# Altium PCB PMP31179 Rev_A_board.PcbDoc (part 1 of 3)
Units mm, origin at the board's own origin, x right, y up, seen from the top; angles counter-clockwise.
Board outline 218.44 x 102.26 mm, 4 copper layers (Top Layer, Mid-Layer 1, Mid-Layer 2, Bottom Layer), stack 1.473 mm thick; 246 components, 120 nets, 592 pads, 115 vias.
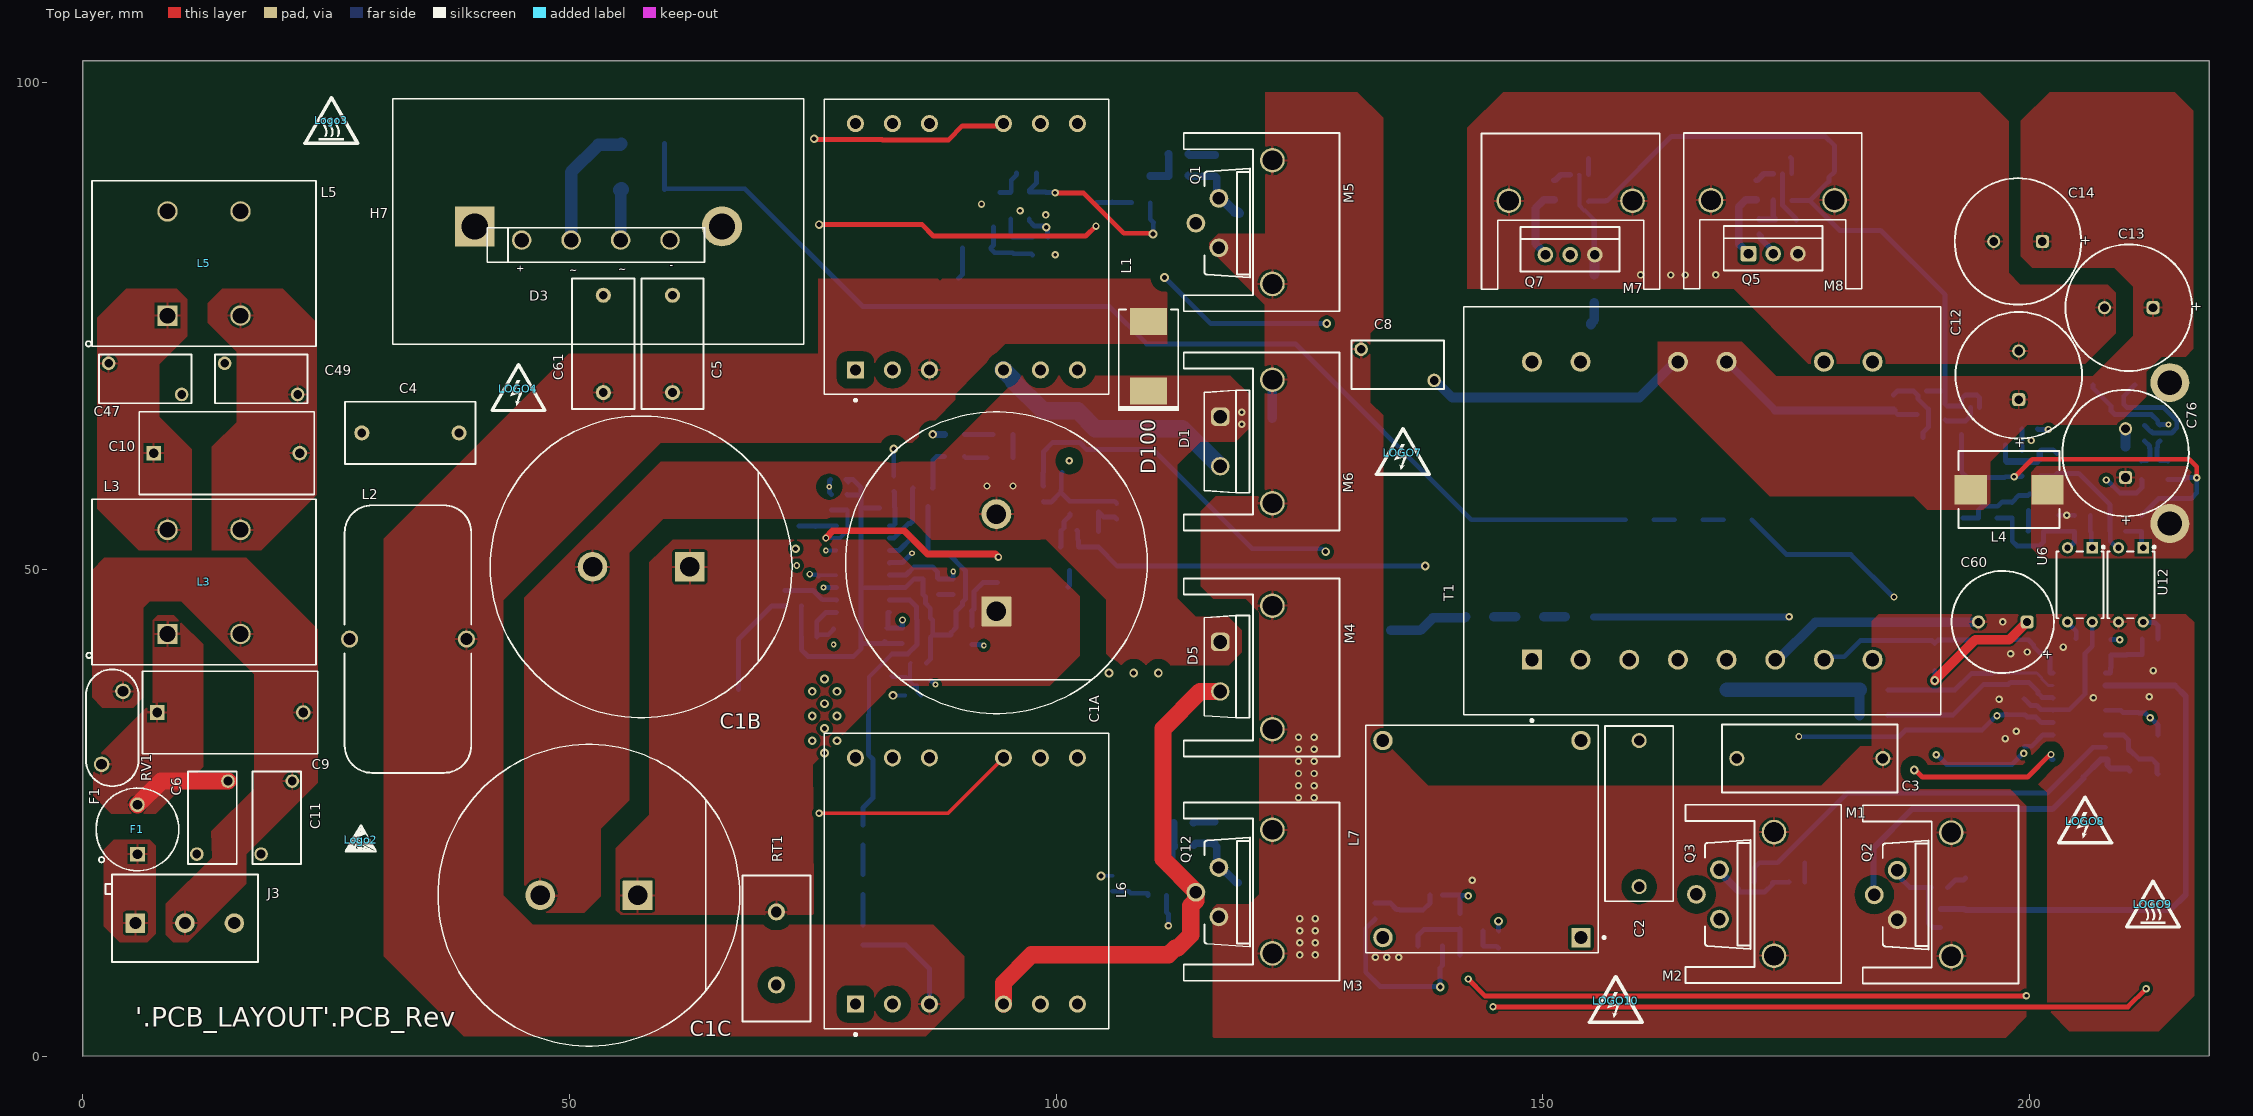
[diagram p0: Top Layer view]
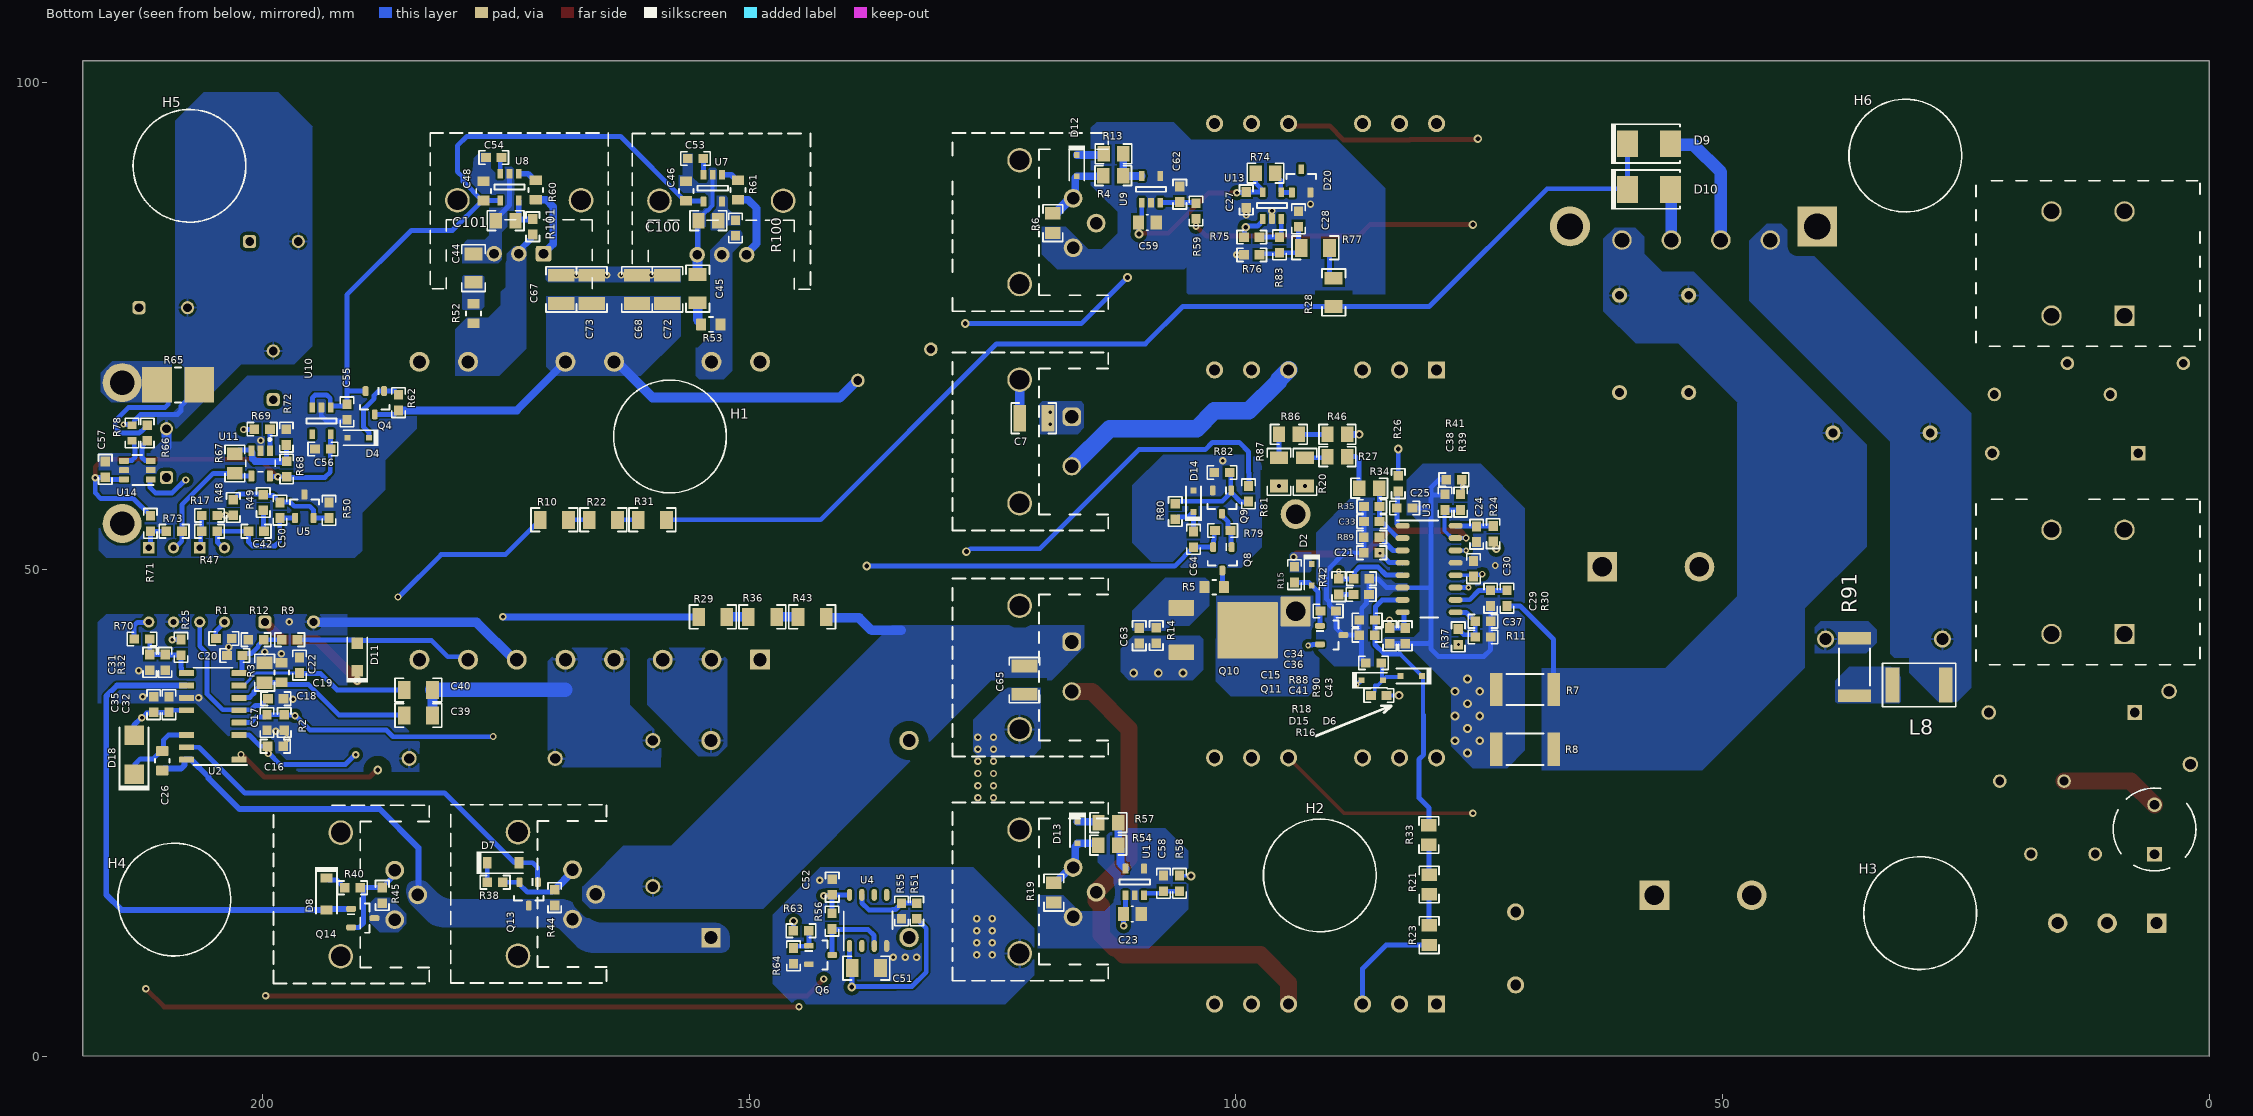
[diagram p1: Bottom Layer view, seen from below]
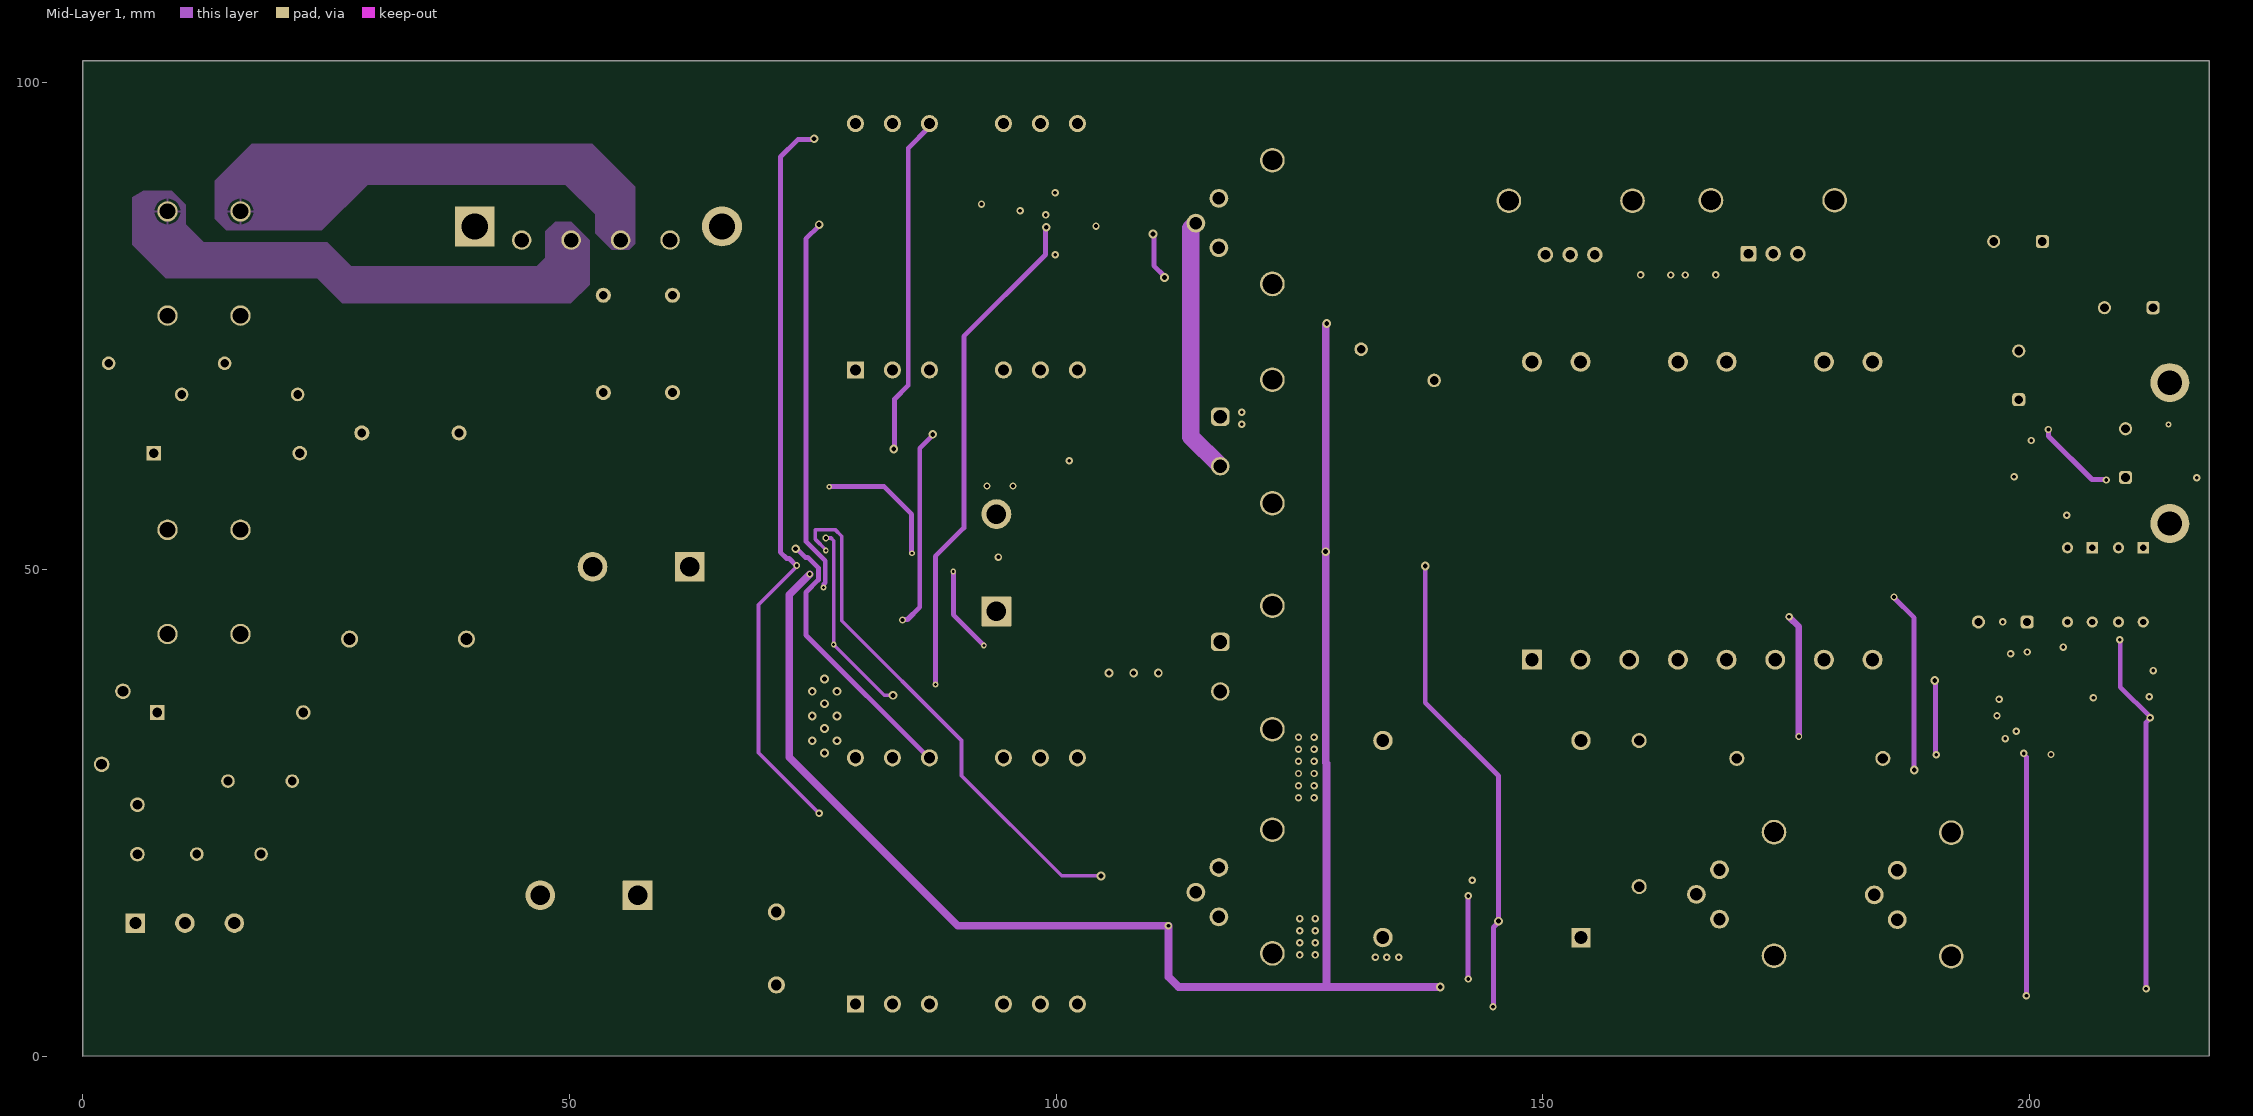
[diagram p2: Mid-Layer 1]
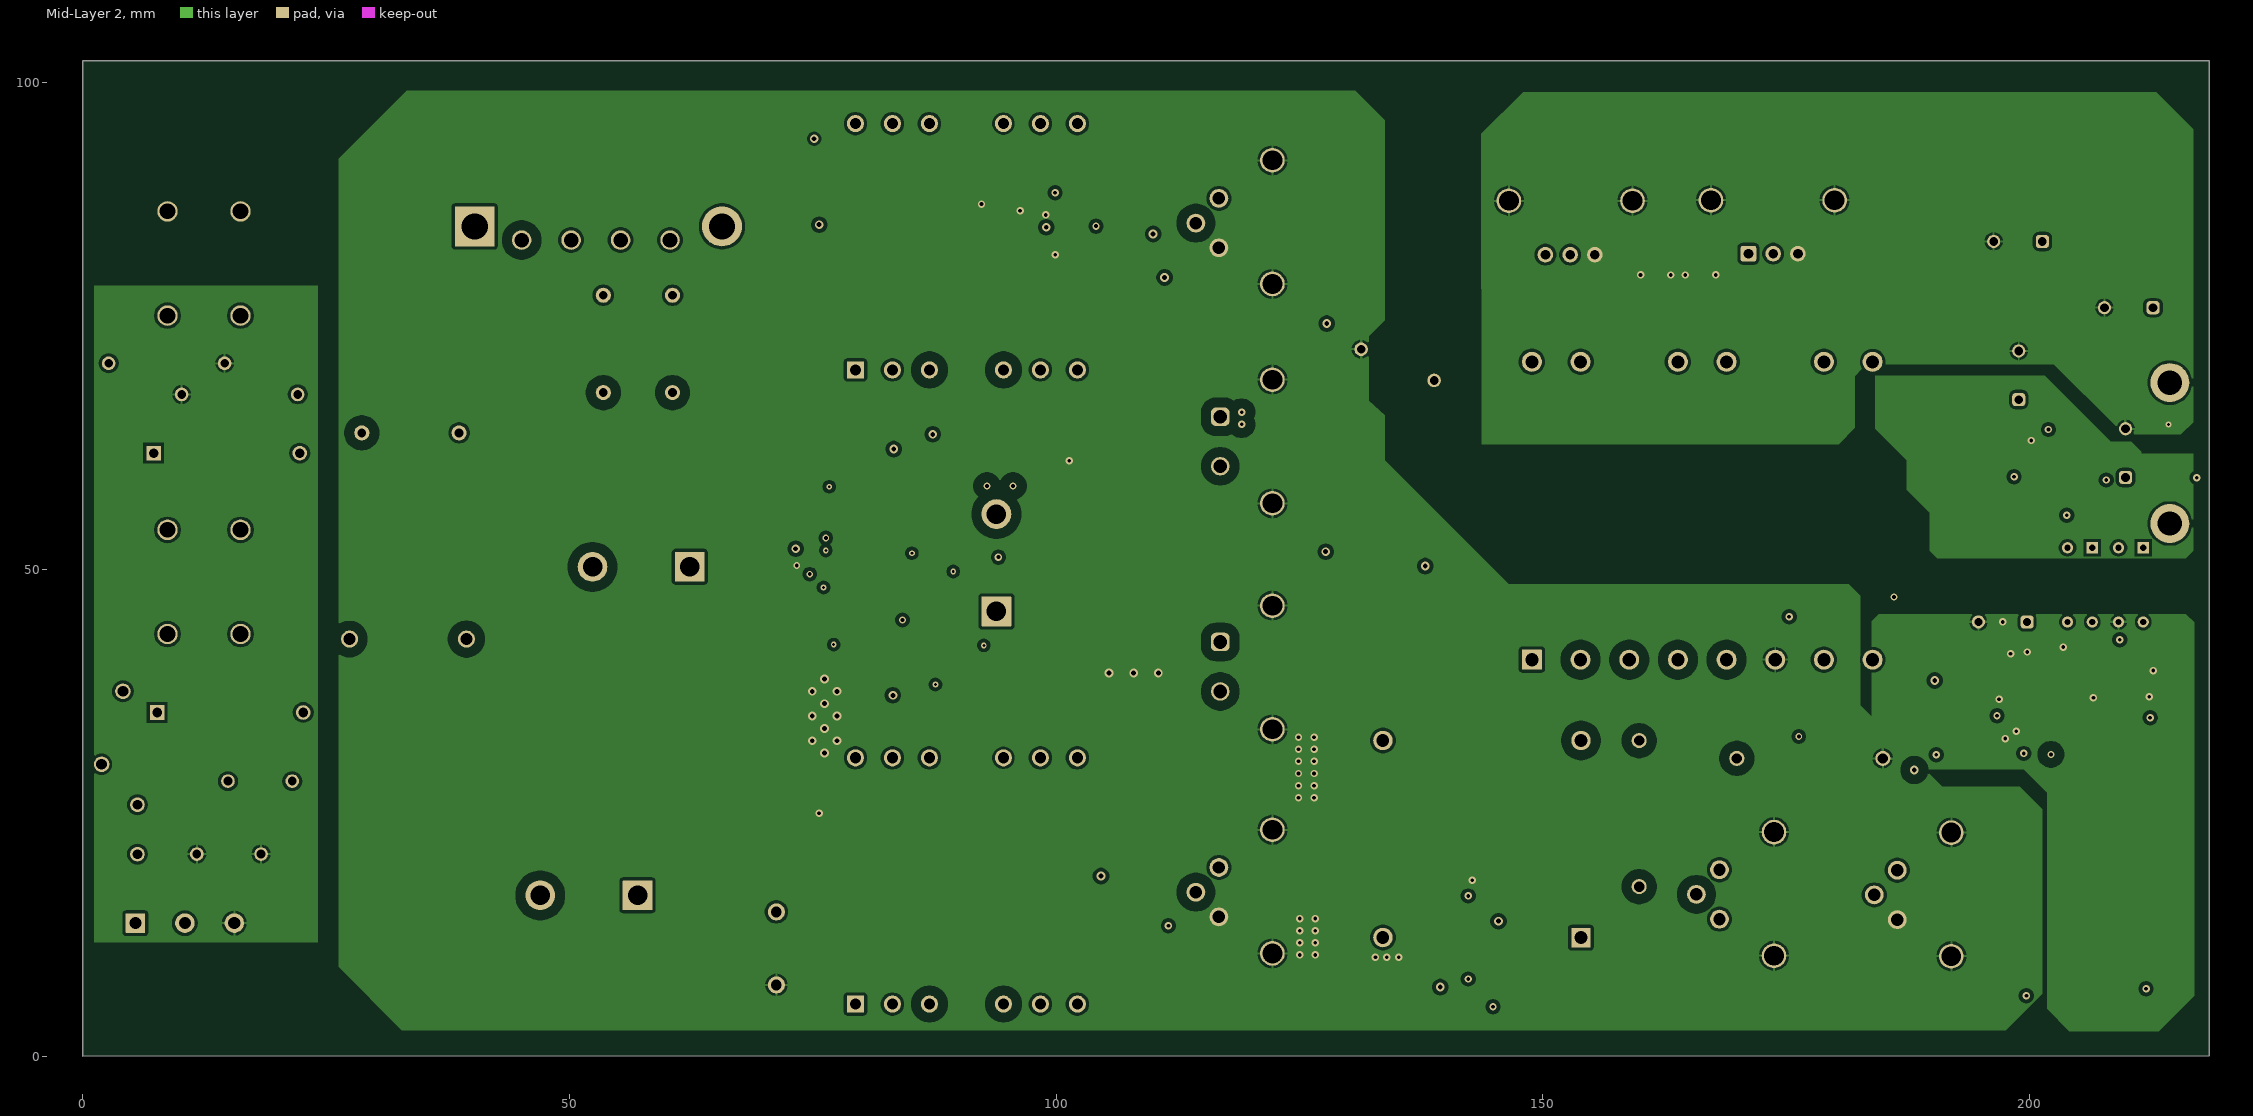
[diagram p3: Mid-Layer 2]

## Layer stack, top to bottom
Top Solder: solder mask 0.18, Solder Resist, Dk 3.5
Top Layer: signal copper 0.07
Dielectric1: prepreg 0.232, FR-4, Dk 4.8
Mid-Layer 1: signal copper 0.0356
Dielectric2: dielectric 0.71, FR-4, Dk 4.8
Mid-Layer 2: signal copper 0.0356
Dielectric3: dielectric 0.32, FR-4, Dk 4.8
Bottom Layer: signal copper 0.07
Bottom Solder: solder mask 0.018, Solder Resist, Dk 3.5

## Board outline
0,0 218.44,0.069 218.44,102.265 0,102.265

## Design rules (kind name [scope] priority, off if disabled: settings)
AcuteAngle [All] p1: minimum=4.50000000000000E+0001 checktracksonly=FALSE
AssemblyTestPointUsage [All] p1: valid=2
BoardOutlineClearance [All] p1: gap=0.381 ignorepadtopadclearanceinfootprint=FALSE
Clearance HV_ALL [InNetClass('HV')] p1: gap=1.016 ignorepadtopadclearanceinfootprint=FALSE
Clearance Clearance_1 [InNet('NetR10_2') vs InNet('PGND')] p2: gap=1.524 ignorepadtopadclearanceinfootprint=FALSE except(0: Arc-Hole Track-Hole SMDPad-Hole THPad-Hole Via-Hole Fill-Hole Poly-Hole Region-Hole Text-Hole)
Clearance Clearance_390V_Discrete [InNet('390V') vs InNet('NetR20_1') Or InNet('NetR86_2') Or InNet('NetQ3_1') Or InNet('SW') Or IsKeepOut] p3: gap=0.61 ignorepadtopadclearanceinfootprint=FALSE except(0: Arc-Hole Track-Hole SMDPad-Hole THPad-Hole Via-Hole Fill-Hole Poly-Hole Region-Hole Text-Hole)
Clearance Clearance_390V [InNet('390V')] p4: gap=1.5 ignorepadtopadclearanceinfootprint=FALSE except(0: Arc-Hole Track-Hole SMDPad-Hole THPad-Hole Via-Hole Fill-Hole Poly-Hole Region-Hole Text-Hole)
Clearance Clearance_MTG [InPadClass('MTG')] p5: gap=0.762 ignorepadtopadclearanceinfootprint=FALSE except(0: Arc-Hole Track-Hole SMDPad-Hole THPad-Hole Via-Hole Fill-Hole Poly-Hole Region-Hole Text-Hole)
Clearance Clearance_Keepouts [IsKeepOut] p6: gap=0.381 ignorepadtopadclearanceinfootprint=FALSE
Clearance Clearance_Poly [InPolygon] p7: gap=0.381 ignorepadtopadclearanceinfootprint=FALSE except(0: Arc-Hole Track-Hole SMDPad-Hole THPad-Hole Via-Hole Fill-Hole Poly-Hole Region-Hole Text-Hole; 0.203: Track-Poly SMDPad-Poly; 0.305: THPad-Poly; 0.508: Poly-Poly)
Clearance [All] p8: gap=0.203 ignorepadtopadclearanceinfootprint=FALSE
ComponentClearance ComponentClearance_MountingHoles_FiducialMarks [InComponentClass('Mounting Holes') vs InComponentClass('FiducialMark')] p1: gap=0.254 collisioncheckmode=3 verticalgap=0.254 showdistances=FALSE
ComponentClearance ComponentClearance_Shunt [InComponentClass('Header') vs InComponentClass('Shunt')] p2: gap=0 collisioncheckmode=3 verticalgap=0 showdistances=FALSE
ComponentClearance ComponentClearance_Logo [InComponentClass('Logo')] p3: gap=0.127 collisioncheckmode=3 verticalgap=0.127 showdistances=FALSE
ComponentClearance ComponentClearance_ScrewToNut [(HasFootprint('NY PMS 440 0025 PH')) vs (HasFootprint('Keystone_1902C'))] p4: gap=0.127 collisioncheckmode=3 verticalgap=0.127 showdistances=FALSE
ComponentClearance ComponentClearance_MountingHoles [InComponentClass('Mounting Holes')] p5: gap=1.27 collisioncheckmode=3 verticalgap=2540 showdistances=FALSE
ComponentClearance ComponentClearance_SmallPassives [HasFootprint('0201*') or HasFootprint('0402*') or HasFootprint('0508') or HasFootprint('0603*') or HasFootprint('0612') or HasFootprint('0805*') or HasFootprint('0815*') or HasFootprint('0830*') or HasFootprint('1206*') or HasFootprint('1210*') or HasFootprint('1808*') or HasFootprint('1812*') or HasFootprint('1825*') or HasFootprint('2010*') or HasFootprint('2220*') or HasFootprint('2225*') or HasFootprint('2512*') or HasFootprint('2728*') or HasFootprint('3518*') vs HasFootprint('0201*') or HasFootprint('0402*') or HasFootprint('0508') or HasFootprint('0603*') or HasFootprint('0612') or HasFootprint('0805*') or HasFootprint('0815*') or HasFootprint('0830*') or HasFootprint('1206*') or HasFootprint('1210*') or HasFootprint('1808*') or HasFootprint('1812*') or HasFootprint('1825*') or HasFootprint('2010*') or HasFootprint('2220*') or HasFootprint('2225*') or HasFootprint('2512*') or HasFootprint('2728*') or HasFootprint('3518*')] p6: gap=0.254 collisioncheckmode=3 verticalgap=0.254 showdistances=FALSE
ComponentClearance ComponentClearance_THtoSMT [IsThruComponent vs IsSMTComponent] p7: gap=0.127 collisioncheckmode=3 verticalgap=0.127 showdistances=FALSE
ComponentClearance ComponentClearance_THtoTH [IsThruComponent vs IsThruComponent] p8: gap=0.254 collisioncheckmode=3 verticalgap=0.254 showdistances=FALSE
ComponentClearance [All] p9: gap=0.254 collisioncheckmode=3 verticalgap=0.254 showdistances=FALSE
DiffPairsRouting [All] p1: maxlimit=2.54 minlimit=0.254 mostfreqgap=0.254 toplayer_minwidth=0.381 toplayer_maxwidth=0.381 toplayer_prefwidth=0.381 midlayer1_minwidth=0.381 midlayer1_maxwidth=0.381 midlayer1_prefwidth=0.381 midlayer2_minwidth=0.381 midlayer2_maxwidth=0.381 midlayer2_prefwidth=0.381 bottomlayer_minwidth=0.381 bottomlayer_maxwidth=0.381 bottomlayer_prefwidth=0.381 maxuncoupledlength=25.4
FabricationTestPointUsage TestPointUsage [All] p1: valid=2 allowmultiple=FALSE
FabricationTestpoint Testpoint [All] p1: side=3 testpointundercomponent=TRUE minsize=1.016 maxsize=2.54 preferedsize=1.524 minholesize=0 maxholesize=1.016 preferedholesize=0.813 testpointgrid=0.025 allowsidetop=TRUE allowsidebottom=TRUE usegrid=TRUE gridtolerance=0
FanoutControl Fanout_LCC [IsLCC] p1: bgadir=Out bgaviamode=Centered fanoutstyle=Auto fanoutdirection=Alternating viagrid=0.025 // Fanout_LCC (Default Rule)
FanoutControl Fanout_BGA [IsBGA] p2: bgadir=Out bgaviamode=Centered fanoutstyle=Auto fanoutdirection=Alternating viagrid=0.025 // Fanout_BGA (Default Rule)
FanoutControl Fanout_Default [All] p4: bgadir=Out bgaviamode=Centered fanoutstyle=Auto fanoutdirection=Alternating viagrid=0.025 // Fanout_Default (Default Rule)
FanoutControl Fanout_Small [(CompPinCount < 5)] p5: bgadir=Out bgaviamode=Centered fanoutstyle=Auto fanoutdirection=OutThenIn viagrid=0.025 // Fanout_Small (Default Rule)
Height [All] p1: minheight=0 maxheight=38 prefheight=12.7
HoleSize [All] p1: absolutevalues=TRUE maxlimit=6.375 minlimit=0.2 maxpercent=80.000 minpercent=20.000
MinimumAnnularRing MinimumAnnularRing_ThermalPadVias [IsVia and InAnyComponent] p1: minimumring=0.15
MinimumAnnularRing [All] p2: minimumring=0.127
MinimumSolderMaskSliver MinimumSolderMaskSliver_Logo [InComponentClass('Logo') vs InComponentClass('Logo')] p1: minsoldermaskwidth=0.018
MinimumSolderMaskSliver [All] p2: minsoldermaskwidth=0.1
PlaneConnect [All] p1: planeconnectstyle=Relief reliefexpansion=0.254 reliefentries=4 reliefconductorwidth=0.254 reliefairgap=0.254
PolygonConnect [All] p1: thpad.connectstyle=Relief thpad.reliefconductorwidth=0.254 thpad.reliefentries=4 thpad.polygonreliefangle="90 Angle" thpad.airgapwidth=0.254 smdpad.connectstyle=Direct smdpad.reliefconductorwidth=0.254 smdpad.reliefentries=4 smdpad.polygonreliefangle="90 Angle" smdpad.airgapwidth=0.254 via.connectstyle=Direct via.reliefconductorwidth=0.254 via.reliefentries=4 via.polygonreliefangle="90 Angle" via.airgapwidth=0.254
RoutingVias [All] p1: holewidth=0.381 width=0.762 viastyle="Through Hole" minholewidth=0.2 minwidth=0.5 maxholewidth=1.016 maxwidth=1.651
RoutingVias ThermalPadVias [IsVia and InAnyComponent] p2: holewidth=0.2 width=0.5 viastyle="Through Hole" minholewidth=0.2 minwidth=0.5 maxholewidth=0.33 maxwidth=0.6
SilkToBoardRegionClearance [Not ((IsComment or IsDesignator) And (Hide <> 'False')) and not InRegion(1000,500,4000,800)] p1:
SilkToSilkClearance SilkToSilkClearance_Pb-FreeLogo [(HasFootprint('Pb-Free_Overlay_Medium') OR HasFootprint('Pb-Free_Overlay_Small')) vs (HasFootprint('Pb-Free_Overlay_Medium') OR HasFootprint('Pb-Free_Overlay_Small'))] p1: silktosilkclearance=0
SilkToSilkClearance [All] p2: silktosilkclearance=0.102
SilkToSolderMaskClearance SilkToComponentPadClearance [IsPad and InAnycomponent] p1: minsilkscreentomaskgap=0.127 clearancetoexposedcopper=TRUE
SilkToSolderMaskClearance "Silk to Solder Mask Opening" [All] p2: minsilkscreentomaskgap=0.102 clearancetoexposedcopper=FALSE
SolderMaskExpansion [All] p1: expansion=0.064 istentingtop=FALSE
Width [All] p1: maxlimit=2.54 minlimit=0.152 preferedwidth=0.254 checkconnectedcopper=TRUE
14 further rules are at their usual default settings.

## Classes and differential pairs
net class HV: NetA NetC2_2 NetC4_1 NetD1_3 NetD5_3 NetL7_6 NetR10_2 VAC Vpfc
component class "PMP30763 Rev_D PFC Schematic": C1A C1B C1C C4 C5 C6 C7 C9 C10 C11 C15 C21 C23 C24 C25 C27 C28 C29 C30 C33 C34 C36 C37 C38 C41 C43 C47 C49 C58 C59 C61 C62 C63 C64 C65 D1 D2 D3 D5 D6 D9 D10 D12 D13 D14 D15 D20 D100 F1 H7 J3 L1 L2 L3 L5 L6 L8 M1 M2 M3 M4 M5 M6 Q1 Q8 Q9 Q10 Q11 Q12 R4 R5 R6 R7 R8 R11 R13 R14 R15 R16 R18 R19 R20 R21 R23 R24 R26 R27 R28 R30 R33 R34 R35 R37 R39 R41 R42 R46 R54 R57 R58 R59 R74 R75 R76 R77 R79 R80 R81 R82 R83 R86 R87 R88 R89 R90 R91 RT1 RV1 U1 U3 U9 U13
component class "PMP30763 Rev_D LLC Schematic": C2 C3 C8 C12 C13 C14 C16 C17 C18 C19 C20 C22 C26 C31 C32 C35 C39 C40 C42 C44 C45 C46 C48 C50 C51 C52 C53 C54 C55 C56 C57 C60 C67 C68 C72 C73 C76 C100 C101 D4 D7 D8 D11 D18 L4 L7 M7 M8 Q2 Q3 Q4 Q5 Q6 Q7 Q13 Q14 R1 R2 R3 R9 R10 R12 R17 R22 R25 R29 R31 R32 R36 R38 R40 R43 R44 R45 R47 R48 R49 R50 R51 R52 R53 R55 R56 R60 R61 R62 R63 R64 R65 R66 R67 R68 R69 R70 R71 R72 R73 R78 R100 R101 T1 U2 U4 U5 U6 U7 U8 U10 U11 U12 U14
component class "PMP30763 Rev_C Hardware": !PCB1 H1 H2 H3 H4 H5 H6 H8 H9 H10 H11 Logo2 LOGO3 LOGO4 LOGO7 LOGO8 LOGO9 LOGO10

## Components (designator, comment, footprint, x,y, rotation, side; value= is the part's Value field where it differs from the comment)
C1A "LGN2V271MELB25" FP-ESMR451VSN221MR25S_RADIAL-MFG 93.853,50.703 r90 top value=270µF
C1B "LGN2V271MELB25" FP-ESMR451VSN221MR25S_RADIAL-MFG 57.361,50.28 r180 top value=270µF
C1C "LGN2V271MELB25" FP-ESMR451VSN221MR25S_RADIAL-MFG 51.99,16.54 r180 top value=270µF
C2 "B32642B6683J" B32652_1800x700x1250 159.887,24.929 r90 top value=0.068uF
C3 "B32642B6683J" B32652_1800x700x1250 177.412,30.607 r0 top value=0.068uF
C4 "ECW-FE2W334K" R46_1300x1200x600 33.655,64.042 r0 top value=0.33µF
C5 "ECW-FE2W334K" R46_1300x1200x600 60.579,73.182 r90 top value=0.33µF
C6 "Capacitor" AY2_950x500_Straight 13.31,24.524 r270 top value=2200pF
C7 "VJ1210Y103KXEAT5Z" 1210 120.746,65.553 r0 bottom value=0.01uF
C8 "Capacitor" AY2_950x500_Straight 135.071,71.039 r180 top value=2200pF
C9 "Capacitor" B32922_14.5mm 15.138,35.319 r0 top value=0.33uF
C10 "Capacitor" B32922_14.5mm 14.783,61.964 r0 top value=0.33uF
C11 "Capacitor" AY2_950x500_Straight 19.914,24.524 r90 top value=2200pF
C12 "EEU-FS1H681B" Panasonic_1250x2500 198.878,69.959 r90 top value=680uF
C13 "EEU-FS1H681B" Panasonic_1250x2500 210.181,76.905 r180 top value=680uF
C14 "EEU-FS1H681B" Panasonic_1250x2500 198.802,83.712 r180 top value=680uF
C15 "Capacitor" 0603#1 90.505,45.733 r180 bottom value=1uF
C16 "C1608X7R1H104K080AA" 0603#1 198.659,31.854 r180 bottom value=0.1uF
C17 "GRM188R71C103KA01D" 0603#1 199.517,34.29 r270 bottom value=0.01uF
C18 "885012006023" 0603#1 198.616,36.733 r180 bottom value=100pF
C19 "Capacitor" 0805_HV1 198.021,39.428 r90 bottom value=3.3pF
C20 "Capacitor" 0603#1 202.837,41.169 r0 bottom value=10pF
C21 "GRM1885C1H122JA01D" 0603#1 86.042,51.731 r0 bottom value=1200pF
C22 "GRM188R71H822KA01D" 0603#1 196.182,40.178 r90 bottom value=8200pF
C23 "08053C225KAT2A" 0805_150 110.617,14.605 r180 bottom value=2.2uF
C24 "C0603C330J5GACTU" 0603#1 75.255,53.631 r270 bottom value=33pF
C25 "C0603C330J5GACTU" 0603#1 82.651,56.316 r180 bottom value=33pF
C26 "Capacitor" 0805_HV1 210.287,30.356 r270 bottom value=0.1uF
C27 "C1608X7R1H104K080AA" 0603#1 98.922,87.984 r270 bottom value=0.1uF
C28 "C1608X7R1H104K080AA" 0603#1 93.563,86.025 r90 bottom value=0.1uF
C29 "C1608X7R1H102K" 0603#1 73.818,47.071 r270 bottom value=1000pF
C30 "Capacitor" 0603#1 75.565,50.093 r270 bottom value=1uF
C31 "C1608X7R1H474K080AC" 0603#1 211.561,40.466 r270 bottom value=0.47uF
C32 "C1608X7R1H104K080AA" 0603#1 209.594,36.134 r90 bottom value=0.1uF
C33 "GRM1885C1H471JA01D" 0603#1 86.028,54.945 r0 bottom value=470pF
C34 "GRM188R71C103KA01D" 0603#1 87.084,49.052 r180 bottom value=0.01uF
C35 "GRM188R61E475KE11D" 0603#1 211.167,36.134 r270 bottom value=4.7uF
C36 "CL10B684KO8NFNC" 0603#1 87.114,47.452 r180 bottom value=0.68uF
C37 "DNP" 0603#1 74.597,44.684 r180 bottom
C38 "GRM188R71H224KAC4D" 0603#1 78.499,56.934 r90 bottom value=0.22uF
C39 "Capacitor" 1206 183.973,35.022 r0 bottom value=150pF
C40 "GRM31A7U3A820JW31D" 1206 183.973,37.638 r0 bottom value=82pF
C41 "C1608X7R2A102K080AA" 0603#1 86.517,43.265 r0 bottom value=1000pF
C42 "06033C473JAT2A" 0603#1 200.629,53.943 r0 bottom value=0.047uF
C43 "Capacitor" 0603#1 82.585,43.19 r270 bottom value=680pF
C44 "12061A331JAT2A" 1206 178.308,80.977 r270 bottom value=330pF
C45 "12061A331JAT2A" 1206 155.276,78.859 r270 bottom value=330pF
C46 "Capacitor" 0805_HV1 156.464,88.9 r90 bottom value=1uF
C47 "Capacitor" AY2_950x500_Straight 6.401,69.591 r0 top value=2200pF
C48 "Capacitor" 0805_HV1 177.276,88.907 r90 bottom value=1uF
C49 "Capacitor" AY2_950x500_Straight 18.317,69.591 r0 top value=2200pF
C50 "Capacitor" 0603#1 198.192,56.102 r270 bottom value=10pF
C51 "Capacitor" 1206 137.951,9.059 r180 bottom value=1uF
C52 "C1608X7R1H104K080AA" 0603#1 141.459,17.386 r90 bottom value=0.1uF
C53 "GRM188R6YA225KA12D" 0603#1 155.501,92.23 r0 bottom value=2.2uF
C54 "GRM188R6YA225KA12D" 0603#1 176.225,92.331 r0 bottom value=2.2uF
C55 "Capacitor" 0603#1 191.309,66.196 r270 bottom value=1uF
C56 "GRM188R61E475KE11D" 0603#1 193.778,62.378 r0 bottom value=4.7uF
C57 "Capacitor" 0603#1 216.132,60.298 r90 bottom value=1uF
C58 "06035A101JAT2A" 0603#1 107.428,17.761 r90 bottom value=100pF
C59 "08053C225KAT2A" 0805_150 109.076,85.67 r180 bottom value=2.2uF
C60 "EEU-FS1V102LB" Panasonic_1000x1250 197.238,44.621 r180 top value=1000µF
C61 "ECW-FE2W334K" R46_1300x1200x600 53.467,73.182 r90 top value=0.33µF
C62 "06035A101JAT2A" 0603#1 105.758,88.559 r90 bottom value=100pF
C63 "C1608X7R1H104K080AA" 0603#1 109.923,43.211 r270 bottom value=0.1uF
C64 "C1608X7R1H474K080AC" 0603#1 104.346,53.104 r90 bottom value=0.47uF
C65 "VJ1210Y103KXEAT5Z" 1210 121.711,38.65 r270 bottom value=0.01uF
C67 "Capacitor" 1210 169.285,78.785 r90 bottom value=4.7uF
C68 "Capacitor" 1210 161.513,78.785 r90 bottom value=4.7uF
C72 "Capacitor" 1210 158.388,78.785 r90 bottom value=4.7uF
C73 "Capacitor" 1210 166.161,78.785 r90 bottom value=4.7uF
C76 "EEU-FS1H681B" Panasonic_1250x2500 209.851,61.969 r90 top value=680uF
C100 "GRM21A5C2E101JW01D" 0805_HV 154.178,85.852 r0 bottom value=100pF
C101 "GRM21A5C2E101JW01D" 0805_HV 175.006,85.852 r0 bottom value=100pF
D1 "MUR860G" TO-220AC 116.848,63.158 r270 top
D2 "BAT54HT1G" SOD-323 92.197,49.479 r270 bottom
D3 "GBU2510-G" GBU 52.705,83.85 r0 top
D4 "BZX384-C15,115" SOD-323 190.137,63.542 r0 bottom value=15V
D5 "MUR860G" TO-220AC 116.848,40.022 r270 top
D6 "BAT54HT1G" SOD-323 81.961,39.07 r0 bottom
D7 "DIODE_SCHOTTKY" SOD-123 175.254,19.883 r180 bottom value=SD103BW-7-F
D8 "DIODE_SCHOTTKY" SOD-123 193.411,16.683 r270 bottom value=SD103BW-7-F
D9 "DIODE" SMB 57.531,93.756 r180 bottom value=RS1MB-13-F
D10 "DIODE" SMB 57.531,89.057 r180 bottom value=RS1MB-13-F
D11 "PMEG6010CEH,115" SOD-123F 190.246,41.021 r90 bottom
D12 "BAT54HT1G" SOD-323 116.326,91.501 r270 bottom
D13 "BAT54HT1G" SOD-323 116.245,22.994 r270 bottom
D14 "BAS20HT1G" SOD-323 104.346,57.029 r90 bottom
D15 "BAT54HT1G" SOD-323 85.979,38.638 r180 bottom
D18 "DIODE" SMA 213.181,30.988 r90 bottom value=US1J-13-F
D20 "LM4040D50QDBZRG4" DBZ0003A_N 93.275,89.94 r90 bottom value=LM4040D50
D100 "S3J-E3/57T" SMC 109.474,71.912 r90 top
F1 "38321000000" FUSE_38321000000 5.613,23.305 r90 top value=10A
H1 "Bumpon" Bumpon_SJ5003Transparent 158.118,63.673 r180 bottom
H2 "Bumpon" Bumpon_SJ5003Transparent 91.364,18.581 r180 bottom
H3 "Bumpon" Bumpon_SJ5003Transparent 29.688,14.709 r180 bottom
H4 "Bumpon" Bumpon_SJ5003Transparent 209.041,16.093 r180 bottom
H5 "Bumpon" Bumpon_SJ5003Transparent 207.484,91.482 r180 bottom
H6 "Bumpon" Bumpon_SJ5003Transparent 31.217,92.532 r180 bottom
H7 "V9733E1-LP" FP-V9733E1-LP_THERMAL_HEATSINK_25MM0_42MM0-MFG 52.959,85.755 r0 top
J3 "ED120/3DS" On-Shore_ED120_3DS 10.482,13.68 r0 top
L1 "750318973r00" FP-750318973r00_PTH_30MM35_29MM2-MFG 90.775,83.165 r90 top value=150µH
L2 "7447076" WE-FI_2750x1300 33.401,42.858 r0 top value=150uH
L3 "7448031501" WURTH_7448031501 12.446,48.73 r0 top value=1mH
L4 "PA2607.301NLT" PA2607NL_7R5mm 197.887,58.21 r0 top value=300nH
L5 "7448031501" WURTH_7448031501 12.446,81.446 r0 top value=1mH
L6 "750318973r00" FP-750318973r00_PTH_30MM35_29MM2-MFG 90.775,18.014 r90 top value=150µH
L7 "750318974r00" FP-750318974r00_PTH_23MM88_23MM36-MFG 143.733,22.322 r180 top value=17uH
L8 "74455122" WE-PD4-S 29.797,38.142 r0 bottom value=22uH
Logo2 "ESD Susceptible" ESD_Overlay_Small 28.53,22.255 r0 top
Logo3 "CAUTION HOT SURFACE" IEC_HotSurface_Small 25.527,96.139 r0 top (schematic designator LOGO3)
LOGO4 "DANGER HIGH VOLTAGE" IEC_HighVoltage_Small 44.755,68.579 r0 top
LOGO7 "DANGER HIGH VOLTAGE" IEC_HighVoltage_Small 135.605,62.008 r0 top
LOGO8 "DANGER HIGH VOLTAGE" IEC_HighVoltage_Small 205.696,24.163 r0 top
LOGO9 "CAUTION HOT SURFACE" IEC_HotSurface_Small 212.665,15.644 r0 top
LOGO10 "DANGER HIGH VOLTAGE" IEC_HighVoltage_Small 157.48,5.715 r0 top
M1 "WA-T220-101E" HEATSINK_WA-T220-101E 190.85,16.632 r180 top
M2 "WA-T220-101E" HEATSINK_WA-T220-101E 172.638,16.683 r180 top
M3 "WA-T220-101E" HEATSINK_WA-T220-101E 121.105,16.919 r180 top
M4 "WA-T220-101E" HEATSINK_WA-T220-101E 121.105,39.942 r180 top
M5 "WA-T220-101E" HEATSINK_WA-T220-101E 121.105,85.695 r180 top
M6 "WA-T220-101E" HEATSINK_WA-T220-101E 121.105,63.158 r180 top
M7 "WA-T220-101E" HEATSINK_WA-T220-101E 152.847,86.79 r270 top
M8 "WA-T220-101E" HEATSINK_WA-T220-101E 173.609,86.844 r270 top
Q1 "IPA60R120P7XKSA1" TO-220AB 116.711,85.593 r270 top
Q2 "IPP60R190P6" TO-220AB 186.405,16.581 r270 top value=IPP60R070CFD7
Q3 "IPP60R190P6" TO-220AB 168.132,16.631 r270 top value=IPP60R070CFD7
Q4 "MMBTA05LT1G" SOT-23 188.451,67.136 r270 bottom
Q5 "CSD19531KCS" KCS0003B#1 173.652,82.452 r90 top
Q6 "MMBT2222LT1G" SOT-23 142.653,10.404 r180 bottom
Q7 "CSD19531KCS" KCS0003B#2 152.793,82.352 r90 top
Q8 "BSS84-7-F" SOT-23 101.375,51.11 r270 bottom
Q9 "MMBT3904LT1G" SOT-23 101.409,56.934 r270 bottom
Q10 "IPD60R360P7SAUMA1" DPAK 102.184,43.777 r180 bottom value=IPD60R360P7S
Q11 "MMBT3906-7-F" SOT-23 90.142,43.269 r180 bottom
Q12 "IPA60R120P7XKSA1" TO-220AB 116.711,16.859 r270 top
Q13 "BC858C-7-F" SOT-23 172.638,16.683 r270 bottom
Q14 "BC858C-7-F" SOT-23 189.681,14.194 r180 bottom
R1 "RMCF0603ZT0R00" 0603#1 203.955,42.921 r0 bottom value=0
R2 "ERJ-3EKF4531V" 0603#1 197.739,34.29 r90 bottom value=4.53k
R3 "CRCW0805150RFKEA" 0805_HV 199.774,39.409 r270 bottom value=150
R4 "ERJ-6GEYJ180V" 0805_HV 112.583,90.48 r0 bottom value=18
R5 "Resistor" 0805_HV1 102.216,48.197 r180 bottom value=18.2
R6 "Resistor" 0805_HV 118.79,85.595 r90 bottom value=10.0k
R7 "Resistor" 2512 70.29,37.69 r180 bottom value=0.03
R8 "Resistor" 2512 70.29,31.544 r180 bottom value=0.03
R9 "CRCW060344K2FKEA" 0603#1 197.198,42.794 r180 bottom value=44.2k
R10 "Resistor" 1206 169.996,55.118 r0 bottom value=1.00k
R11 "RMCF0603ZT0R00" 0603#1 74.597,43.087 r0 bottom value=0
R12 "RC0603FR-078K06L" 0603#1 200.653,42.794 r180 bottom value=8.06k
R13 "RC0805JR-072R2L" 0805_HV 112.558,92.702 r0 bottom value=2.2
R14 "ERJ-3EKF4992V" 0603#1 108.16,43.225 r270 bottom value=49.9k
R15 "CRCW0603100KFKEA" 0603#1 93.955,49.479 r270 bottom value=100k
R16 "RC0603FR-0744K2L" 0603#1 85.302,37.056 r180 bottom value=44.2k
R17 "RC0603FR-0712KL" 0603#1 205.425,55.569 r180 bottom value=12.0k
R18 "CRCW060351K1FKEA" 0603#1 85.852,40.416 r180 bottom value=51.1k
R19 "Resistor" 0805_HV 118.688,16.81 r90 bottom value=10.0k
R20 "CRCW12063M00JNEA" 1206 92.888,60.033 r270 bottom value=3.0Meg
R21 "RC0805FR-072M2L" 0805_HV 80.137,17.653 r270 bottom value=2.20Meg
R22 "Resistor" 1206 164.967,55.118 r0 bottom value=1.00k
R23 "RC0805FR-072M2L" 0805_HV 80.137,12.446 r270 bottom value=2.20Meg
R24 "CRCW06036K81FKEA" 0603#1 73.559,53.687 r270 bottom value=6.81k
R25 "RT0603DRE07213KL" 0603#1 208.349,42.007 r90 bottom value=213k
R26 "CRCW06036K81FKEA" 0603#1 83.31,58.833 r90 bottom value=6.81k
R27 "Resistor" 0805_HV 89.56,61.604 r0 bottom value=2.74Meg
R28 "Resistor" 1206 89.94,78.474 r90 bottom value=511k
R29 "Resistor" 1206 153.726,45.145 r180 bottom value=330k
R30 "Resistor" 0603#1 72.14,47.071 r90 bottom value=100
R31 "Resistor" 1206 159.938,55.118 r0 bottom value=1.00k
R32 "RC0603FR-07120KL" 0603#1 209.986,40.466 r90 bottom value=120k
R33 "RC0805FR-072M2L" 0805_HV 80.158,22.733 r90 bottom value=2.20Meg
R34 "Resistor" 0805_HV 86.282,58.374 r0 bottom value=2.74Meg
R35 "RT0603DRE07215KL" 0603#1 86.028,56.469 r180 bottom value=215k
R36 "Resistor" 1206 148.621,45.145 r180 bottom value=330k
R37 "DNP" 0603#1 77.135,43.087 r270 bottom
R38 "Resistor" 0603#1 176.092,17.877 r180 bottom value=22
R39 "RC0603FR-07200KL" 0603#1 76.899,56.934 r270 bottom value=200k
R40 "Resistor" 0603#1 190.735,17.322 r180 bottom value=22
R41 "CRCW060380K6FKEA" 0603#1 77.586,59.238 r0 bottom value=80.6k
R42 "RC0603FR-0727KL" 0603#1 89.416,48.252 r270 bottom value=27.0k
R43 "CRCW1206330KJNEA" 1206 143.516,45.145 r180 bottom value=330k
R44 "Resistor" 0603#1 169.971,16.302 r90 bottom value=4.7k
R45 "Resistor" 0603#1 187.675,16.531 r90 bottom value=4.7k
R46 "Resistor" 0805_HV 89.56,63.894 r0 bottom value=2.74Meg
R47 "Resistor" 0603#1 205.43,53.944 r0 bottom value=6.04k
R48 "Resistor" 0603#1 202.993,56.382 r270 bottom value=147k
R49 "Resistor" 0603#1 199.898,56.889 r90 bottom value=10.0k
R50 "RC0603FR-0713K3L" 0603#1 193.163,56.089 r270 bottom value=13.3k
R51 "CRCW0603113KFKEA" 0603#1 132.76,14.93 r270 bottom value=113k
R52 "Resistor" 0805_HV1 178.308,76.312 r90 bottom value=10
R53 "Resistor" 0805_HV1 153.924,75.184 r0 bottom value=10
R54 "ERJ-6GEYJ180V" 0805_HV 113.099,21.689 r0 bottom value=18
R55 "Resistor" 0603#1 134.335,14.93 r90 bottom value=10.0k
R56 "RT0603BRD07100KL" 0603#1 141.47,13.885 r90 bottom value=100k
R57 "RC0805JR-072R2L" 0805_HV 113.085,24.002 r0 bottom value=2.2
R58 "ERJ-3EKF1000V" 0603#1 105.777,17.761 r270 bottom value=100
R59 "ERJ-3EKF1000V" 0603#1 104.084,86.838 r270 bottom value=100
R60 "Resistor" 0805_HV1 171.907,89.003 r90 bottom value=4.7
R61 "Resistor" 0805_HV1 151.137,89.001 r270 bottom value=4.7
R62 "RC0603FR-076K81L" 0603#1 186.012,67.154 r270 bottom value=6.81k
R63 "CRCW0603113KFKEA" 0603#1 144.66,12.889 r180 bottom value=113k
R64 "Resistor" 0603#1 145.434,10.32 r90 bottom value=10.0k
R65 "WSL2512L5000FEA18" WSL2512_-0005 208.657,68.98 r0 bottom value=0.0005
R66 "CRCW060310R0FKEAHP" 0603#1 211.812,64.027 r270 bottom value=10.0
R67 "CRCW08051M00FKEA" 0805_HV 202.815,60.903 r270 bottom value=1.00Meg
R68 "MCT06030C1004FP500" 0603#1 197.503,60.333 r270 bottom value=1.00Meg
R69 "ERJ-3EKF3303V" 0603#1 200.021,64.43 r180 bottom value=330k
R70 "Resistor" 0603#1 212.362,42.871 r180 bottom value=487k
R71 "Resistor" 0603#1 211.502,54.743 r90 bottom value=6.04k
R72 "RT0603DRE07234KL" 0603#1 197.532,63.61 r270 bottom value=234k
R73 "Resistor" 0603#1 209.063,53.944 r0 bottom value=6.04k
R74 "Resistor" 0805_HV 96.941,90.728 r0 bottom value=10.0k
R75 "CRCW06031M10FKEA" 0603#1 98.354,84.154 r0 bottom value=1.10Meg
R76 "CRCW060390K9FKEA" 0603#1 98.354,82.331 r180 bottom value=90.9k
R77 "Resistor" 1206 91.825,83.055 r0 bottom value=511k
R78 "CRCW060310R0FKEAHP" 0603#2 213.388,64.027 r270 bottom value=10.0
R79 "CRCW0603100KFKEA" 0603#1 101.34,54.026 r180 bottom value=100k
R80 "RC0603FR-0775KL" 0603#1 106.22,55.97 r270 bottom value=75.0k
R81 "CRCW0603390KJNEA" 0603#1 98.679,57.785 r90 bottom value=390k
R82 "RC0603FR-0749K9L" 0603#1 101.409,59.973 r180 bottom value=49.9k
R83 "ERJ-3EKF2202V" 0603#1 95.513,83.354 r90 bottom value=22.0k
R86 "Resistor" 0805_HV 94.539,63.894 r0 bottom value=2.74Meg
R87 "CRCW12062M70JNEA" 1206 95.555,60.033 r270 bottom value=2.7Meg
R88 "CRCW060397K6FKEA" 0603#1 86.503,44.81 r0 bottom value=97.6k
R89 "RC0603FR-0782KL" 0603#1 86.042,53.332 r180 bottom value=82.0k
R90 "CRCW0603130KFKEA" 0603#1 84.176,43.19 r90 bottom value=130k
R91 "CRCW251247R0JNEG" 2512 36.449,40.005 r90 bottom value=47
R100 "ERJ-3EKF1001V" 0603#1 151.384,85.09 r270 bottom value=1.00k
R101 "ERJ-3EKF1001V" 0603#1 172.212,85.217 r270 bottom value=1.00k
RT1 "B57237S0220M000" S237 71.247,11.079 r90 top value=22
RV1 "Varistor_MetalOxide" VAR_S10K275E2 3.023,33.744 r270 top value=275V
T1 "750318984r00" FP-750318984r00_PTH_41MM9_49MM0-MFG 166.364,56.044 r90 top
U1 "UCC27517DBVR" DBV0005A_N 110.371,17.907 r90 bottom value=UCC27517
U2 "UCC256404ADDBR" DDB0014A 205.086,34.918 r0 bottom value=UCC256404
U3 "UCC28064ADR" D0016A_N 80.137,50.06 r180 bottom value=UCC28064A
U4 "LP2951ACMX/NOPB" D0008A_L 137.773,13.961 r90 bottom value=LP2951-N
U5 "TL431LIAIDBZR" DBZ0003A_N 195.678,56.508 r90 bottom
U6 "Opto-Isolator" DIP-4 205.163,48.431 r270 top value=VO618A-3
U7 "UCC24612-1DBVR" DBV0005A_N 153.723,89.182 r270 bottom value=UCC24612-1
U8 "UCC24612-1DBVR" DBV0005A_N 174.609,89.288 r270 bottom value=UCC24612-1
U9 "UCC27517DBVR" DBV0005A_N 108.704,89.067 r90 bottom value=UCC27517
U10 "LP2981-50" DBV0005A_N 193.929,65.274 r270 bottom
U11 "TL331BIDBVR" DBV0005A-MFG 200.175,60.915 r270 bottom
U12 "Opto-Isolator" DIP-4 210.395,48.431 r270 top value=VO618A
U13 "TLV171IDBVR" DBV0005A_N 96.28,87.4 r90 bottom value=TLV171I
U14 "INA181A4IDBV" DBV0006A_N 212.837,60.22 r0 bottom value=INA181A

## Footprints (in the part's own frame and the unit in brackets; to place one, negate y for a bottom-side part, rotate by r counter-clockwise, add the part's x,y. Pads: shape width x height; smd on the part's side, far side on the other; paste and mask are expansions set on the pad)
0603#1 [mm] "0603 from SM-752 data"
  rect 1x0.95 smd: 1(-0.8,0) 2(0.8,0)
  silkscreen extent -1.52,-0.69 1.52,0.69, body extent -0.87,-0.47 0.87,0.47, height 1
0603#2 [mm] "0603 from SM-752 data"
  rect 0.8x0.95 smd: 1(-0.8,0) 2(0.8,0)
  silkscreen extent -1.52,-0.69 1.52,0.69, body extent -0.87,-0.47 0.87,0.47, height 1
0805_150 [mm] "0805 / 1.5 mm height"
  rect 1.15x1.45 smd: 1(-0.9,0) 2(0.9,0)
  silkscreen extent -0.1,-0.8 0.1,0.8, body extent -1.1,-0.72 1.1,0.72, height 1.5
0805_HV [mil] "0805 with 30mil clearance between pads"
  rect 50x63 smd: 1(-40,0) 2(40,0)
  silkscreen extent -74,-40 74,40, body extent -43,-29 43,29, height 57
0805_HV1 [mm] "Custom footprint based on analyzing multiple manufacturer recommendations"
  rrect10% 1x1.25 smd: 1(-1,0) 2(1,0)
  silkscreen extent -0.2,-0.75 0.2,0.75, body extent -1.1,-0.72 1.1,0.73, height 1.45
1206 [mm] "1206 from SM-752 data"
  rect 1.3x1.85 smd: 1(-1.45,0) 2(1.45,0)
  silkscreen extent -2.4,-1.21 2.4,1.21, body extent -1.7,-0.9 1.7,0.9, height 1.35
1210 [mm] "1210 from SM-752 data"
  rect 1.3x2.7 smd: 1(-1.45,0) 2(1.45,0)
  silkscreen extent -2.32,-1.57 2.32,1.57, body extent -1.7,-1.35 1.7,1.35, height 1.35
2512 [mm] "Chip Resistor, Body 6.3x3.2mm, IPC Medium Density"
  rect 1.3x3.4 smd: 1(-2.95,0) 2(2.95,0)
  silkscreen extent -1.9,-1.6 1.9,1.6, body extent -3.22,-1.67 3.22,1.67, height 0.71
AY2_950x500_Straight [mm] "TH, 2-Leads, 9.5x5mm, Pin Spacing 7.5mm"
  round 1.4 hole 0.9: 1(-3.75,1.6) 2(3.75,-1.6)
  silkscreen extent -4.75,-2.5 4.75,2.5, body extent -4.74,-2.5 4.75,2.5, height 12.5
B32652_1800x700x1250 [mm] "TH, 2-Leads, Body 18x7mm, Pin Spacing 15mm"
  round 1.55 hole 1.05: 1(-7.5,0) 2(7.5,0)
  silkscreen extent -9,-3.5 9,3.5, body extent -9,-3.5 9,3.5, height 12.5
B32922_14.5mm [mm] "Epcos film capacitors, 15mm spacing"
  rect 1.5x1.5 hole 1: 1(-7.5,0)
  round 1.5 hole 1: 2(7.5,0)
  silkscreen extent -9,-4.25 9,4.25, body extent -9,-4.25 9,4.25, height 14.5
Bumpon_SJ5003Transparent [mil] "3M Hemispherical Bumpon transparent"
  round 1 on Mech4: 0(0,0)
  silkscreen extent -228,-228 228,228, body extent -219,-219 219,219, height 197
D0008A_L [mm] "SOIC, 8-Leads, Body 4.9x3.9mm, Pitch 1.27mm, IPC High Density"
  oval 1.25x0.55 smd: 1(-2.625,1.905) 2(-2.625,0.635) 3(-2.625,-0.635) 4(-2.625,-1.905) 5(2.625,-1.905) 6(2.625,-0.635) 7(2.625,0.635) 8(2.625,1.905)
  silkscreen extent -3.1,-2.5 0.9,2.5, body extent -3,-2.45 3,2.45, height 1.63
D0016A_N [mm] "SOIC, 16-Leads, Body 9.9x3.9mm, Pitch 1.27mm, IPC Medium Density"
  oval 1.45x0.6 smd: 1(-2.725,4.445) 2(-2.725,3.175) 3(-2.725,1.905) 4(-2.725,0.635) 5(-2.725,-0.635) 6(-2.725,-1.905) 7(-2.725,-3.175) 8(-2.725,-4.445) 9(2.725,-4.445) 10(2.725,-3.175) 11(2.725,-1.905) 12(2.725,-0.635) 13(2.725,0.635) 14(2.725,1.905) 15(2.725,3.175) 16(2.725,4.445)
  silkscreen extent -3.3,-5 0.9,5, body extent -3,-4.95 3,4.95, height 1.6
DBV0005A-MFG [mm]
  rrect17% 1.1x0.6 smd paste+0 mask+0: 1(-1.3,0.95) 2(-1.3,0) 3(-1.3,-0.95) 4(1.3,-0.95) 5(1.3,0.95)
  silkscreen extent -2.57,-1.53 0.87,1.53, body extent -1.4,-1.45 1.4,1.45, height 1.45
DBV0005A_N [mm] "SOT23, 5-Leads, Body 2.9x1.6mm, Pitch 0.95mm, Lead Span 2.8mm, IPC Medium Density"
  rrect17% 1x0.6 smd: 1(-1.375,0.95) 2(-1.375,0) 3(-1.375,-0.95) 4(1.375,-0.95) 5(1.375,0.95)
  silkscreen extent -0.25,-1.55 0.25,1.55, body extent -1.42,-1.46 1.42,1.46, height 1.09
DBV0006A_N [mm] "SOT23, 6-Leads, Body 2.9x1.6mm, Pitch 0.95mm, Lead Span 2.8mm, IPC Medium Density"
  rrect17% 1x0.6 smd: 1(-1.375,0.95) 2(-1.375,0) 3(-1.375,-0.95) 4(1.375,-0.95) 5(1.375,0) 6(1.375,0.95)
  silkscreen extent -1.68,-1.55 0.5,1.55, body extent -1.42,-1.46 1.42,1.46, height 1.12
DBZ0003A_N [mm] "SOT23, 3-Leads, Body 2.9x1.3mm, Pitch 0.95mm, Lead Span 2.4mm, IPC Medium Density"
  rrect17% 1x0.6 smd: 1(-1.2,0.95) 2(-1.2,-0.95) 3(1.2,0)
  silkscreen extent 0.2,-1.5 0.7,1.5, body extent -1.26,-1.46 1.26,1.46, height 0.98
DDB0014A [mm] "SMD, 14-Leads, Body 3.9x9.9mm, Pitch 1.27mm"
  rrect17% 1.55x0.6 smd: 1(-2.7,4.445) 3(-2.7,1.905) 4(-2.7,0.635) 5(-2.7,-0.635) 6(-2.7,-1.905) 7(-2.7,-3.175) 8(-2.7,-4.445) 9(2.7,-4.445) 10(2.7,-3.175) 11(2.7,-1.905) 12(2.7,-0.635) 14(2.7,1.905) 15(2.7,3.175) 16(2.7,4.445)
  silkscreen extent -3.5,-5 2,5, body extent -3.01,-4.95 3.01,4.95, height 1.75
DIP-4 [mm] "DIP, 4-Leads, Body 6.86x4.83mm, Pitch 2.54mm"
  rect 1.15x1.15 hole 0.65: 1(-3.81,1.27)
  round 1.15 hole 0.65: 2(-3.81,-1.27) 3(3.81,-1.27) 4(3.81,1.27)
  silkscreen extent -4,-2.41 3.43,2.52, body extent -4.02,-2.41 4.02,2.41, height 5.59
DPAK [mm] "D-PAK, 3-Pads, Body 6.22x6.73mm (max), TO-252AA using nominal STEP model"
  rrect6% 2.6x1.6 smd: 1(-3.4,2.28) 3(-3.4,-2.28)
  rrect2% 6.2x5.8 smd paste-3: 2(3.4,0)
  body extent -3.86,-3.29 5.84,3.29, height 2.48
ESD_Overlay_Small [mm]
  silkscreen extent -1.58,-1.23 1.62,1.55
FP-750318973r00_PTH_30MM35_29MM2-MFG [mm]
  rrect6% 1.75x1.75 hole 1.15 paste-1000 mask+0: 1(-12.65,11.4)
  round 1.75 hole 1.15 paste-1000 mask+0: 2(-12.65,7.6) 3(-12.65,3.8) 4(-12.65,-3.8) 5(-12.65,-7.6) 6(-12.65,-11.4) 7(12.65,-11.4) 8(12.65,-7.6) 9(12.65,-3.8) 10(12.65,3.8) 11(12.65,7.6) 12(12.65,11.4)
  silkscreen extent -15.9,-14.6 15.17,14.6, body extent -15.28,-14.7 15.28,14.7, height 0.25
FP-750318974r00_PTH_23MM88_23MM36-MFG [mm]
  rrect5% 2x2 hole 1.3 paste-1000 mask+0: 1(-10.175,10.12)
  round 2 hole 1.3 paste-1000 mask+0: 6(-10.175,-10.12) 7(10.175,-10.12) 14(10.175,10.12)
  silkscreen extent -12.67,-11.68 11.94,11.68, body extent -12.04,-11.78 12.04,11.78, height 0.25
FP-750318984r00_PTH_41MM9_49MM0-MFG [mm]
  rrect5% 2.05x2.05 hole 1.35 paste-1000 mask+0: 1(-15.3,17.5)
  round 2.05 hole 1.35 paste-1000 mask+0: 2(-15.3,12.5) 3(-15.3,7.5) 4(-15.3,2.5) 5(-15.3,-2.5) 6(-15.3,-7.5) 7(-15.3,-12.5) 8(-15.3,-17.5) 9(15.3,-17.5) 10(15.3,-12.5) 12(15.3,-2.5) 13(15.3,2.5) 15(15.3,12.5) 16(15.3,17.5)
  silkscreen extent -21.67,-24.5 20.95,24.5, body extent -21.05,-24.6 21.05,24.6, height 0.25
FP-ESMR451VSN221MR25S_RADIAL-MFG [mm]
  rrect3% 3.05x3.05 hole 2 paste-1000 mask+0: 1(-5,0)
  round 3.05 hole 2 paste-1000 mask+0: 2(5,0)
  silkscreen extent -15.5,-15.5 15.5,15.5, body extent -15.6,-15.6 15.6,15.6, height 0.25
FP-V9733E1-LP_THERMAL_HEATSINK_25MM0_42MM0-MFG [mm]
  rrect2% 4.1x4.1 hole 2.7 paste-1000 mask+0: 1(-12.7,-0.5)
  round 4.1 hole 2.7 paste-1000 mask+0: 2(12.7,-0.5)
  silkscreen extent -21.12,-12.62 21.12,12.62, body extent -21.22,-12.73 21.22,12.73, height 0.25
FUSE_38321000000 [mm] "LITTELFUSE_383, TH-2P"
  rect 1.5x1.5 / inner round 1.5 / far side rect 1.5x1.5 hole 1: 1(-2.54,0)
  round 1.5 hole 1: 2(2.54,0)
  silkscreen extent -4.25,-4.25 4.25,4.25, body extent -4.25,-4.25 4.25,4.25, height 8
GBU [mm] "Comchip / Diodes Inc diode bridge"
  round 2 hole 1.5: 1(-7.62,0) 2(-2.54,0) 3(2.54,0) 4(7.62,0)
  silkscreen extent -11.15,-2.28 11.15,1.28, body extent -11.15,-2.28 11.15,1.28, height 21.55
HEATSINK_WA-T220-101E [mm] "HEATSINK VERT ALUM BLACK TO-220"
  round 2.532 hole 2.032: 1(-1.1,-6.35) 2(-1.1,6.35)
  silkscreen extent -8,-9.15 8,9.15, body extent -7.98,-9.15 8,9.15, height 32.3
IEC_HighVoltage_Small [mm]
  silkscreen extent -2.72,-2.24 2.72,2.47
IEC_HotSurface_Small [mm]
  silkscreen extent -2.72,-2.36 2.72,2.35
KCS0003B#1 [mm] "Flange Mount, 3-Leads, Body 10.16x4.51mm, Pitch 2.54mm"
  rrect25% 1.6x1.6 hole 1: 1(0,2.54)
  round 1.6 hole 1: 2(0,0) 3(0,-2.54)
  silkscreen extent -1.71,-5.08 2.86,5.08, body extent -1.71,-5.09 2.86,5.08, height 18.63
KCS0003B#2 [mm] "Flange Mount, 3-Leads, Body 10.16x4.51mm, Pitch 2.54mm"
  round 1.6 hole 1: 1(0,2.54) 2(0,0) 3(0,-2.54)
  silkscreen extent -1.71,-5.08 2.86,5.08, body extent -1.71,-5.09 2.86,5.08, height 18.63
On-Shore_ED120_3DS [mm] "ONSHORE"
  rrect5% 2x2 hole 1.25: 1(-5.08,0)
  round 2 hole 1.25: 2(0,0) 3(5.08,0)
  silkscreen extent -8.14,-4 7.5,5, body extent -8.32,-4 7.62,5, height 13
PA2607NL_7R5mm [mm] "SMD, 2-Leads, Body 10.31x7.5mm"
  rect 3.3x3.05 smd: 1(-3.935,0) 2(3.935,0)
  silkscreen extent -5.2,-3.95 5.2,3.95, body extent -5.44,-3.95 5.44,3.95, height 7.5
Panasonic_1000x1250 [mm] "TH, 2-Leads, Dia 10mm, Lead Spacing 5mm"
  rrect50% 1.35x1.35 hole 0.85: 1(-2.5,0)
  round 1.35 hole 0.85: 2(2.5,0)
  silkscreen extent -5.25,-5.25 5.25,5.25, body extent -5.25,-5.25 5.26,5.25, height 13.51
Panasonic_1250x2500 [mm] "TH, 2-Leads, Dia 12.5mm, Lead Spacing 5mm"
  rrect50% 1.35x1.35 hole 0.9: 1(-2.5,0)
  round 1.35 hole 0.9: 2(2.5,0)
  silkscreen extent -6.5,-6.5 6.5,6.5, body extent -6.5,-6.5 6.51,6.5, height 27.01
R46_1300x1200x600 [mm] "KEMET"
  round 1.55 hole 0.9: 1(-5,0) 2(5,0)
  silkscreen extent -6.7,-3.2 6.7,3.2, body extent -6.6,-3.1 6.6,3.1, height 12.1
S237 [mm] "EPCOS"
  round 1.75 hole 1.1: 1(-3.75,0) 2(3.75,0)
  silkscreen extent -7.5,-3.5 7.5,3.5, body extent -7.47,-3.5 7.47,3.5, height 21.99
SMA [mm] "Molded Diode, 2-Leads, Body 4.3x2.6mm, IPC Medium Density, based on OnSemi component dimensions and land pattern"
  rect 2x2 smd: 1(-2,0) 2(2,0)
  silkscreen extent -3.66,-1.57 2.79,1.57, body extent -2.6,-1.3 2.6,1.3, height 2.42
SMB [mm] "Molded Diode, 2-Leads, Body 5.4x3.6mm, IPC Medium Density, based on OnSemi component dimensions"
  rect 2.159x2.743 smd: 1(-2.21,0) 2(2.21,0)
  silkscreen extent -3.94,-2.08 3.18,2.08, body extent -2.7,-1.8 2.7,1.8, height 2.32
SMC [mil] "Molded Diode, 2-Leads, Body 6.9x5.8mm, IPC Medium Density, based on OnSemi component dimensions and land patterns"
  rect 110x150 smd: 1(-140.49,0) 2(140.49,0)
  silkscreen extent -221,-123 189,124, body extent -156,-116 156,116, height 91
SOD-123 [mm] "On Semi recommended land pattern"
  rect 0.915x1.22 smd: 1(-1.637,0) 2(1.637,0)
  silkscreen extent -2.74,-1.17 2.03,1.17, body extent -1.93,-0.9 1.93,0.9, height 1.35
SOD-123F [mm] "NXP recommended land pattern"
  rect 1.2x1.2 smd paste-0.05: 1(-1.4,0) 2(1.4,0)
  silkscreen extent -2.64,-1.12 2.01,1.12, body extent -1.8,-0.85 1.8,0.85, height 1.2
SOD-323 [mm] "NXP recommended land pattern"
  rect 0.6x0.6 smd paste-0.05: 1(-1.1,0) 2(1.1,0)
  silkscreen extent -2.06,-0.86 1.53,0.86, body extent -1.3,-0.67 1.3,0.68, height 1.1
SOT-23 [mm] "SOT23, 3-Leads, Body 2.9x1.3mm, Pitch 0.95mm, Lead Span 2.5mm, IPC Medium Density"
  rrect50% 1x0.6 smd: 1(-1.2,0.95) 2(-1.2,-0.95) 3(1.2,0)
  silkscreen extent -1.63,-1.5 0.7,1.5, body extent -1.16,-1.45 1.21,1.45, height 1
TO-220AB [mil] "Copied from Altium's version of TO3B"
  round 76 hole 50: 1(-100,0) 2(-0.07,-93.17) 3(100,0)
  silkscreen extent -221,-59 221,126, body extent -221,-59 221,126, height 765
TO-220AC [mm]
  rrect50% 1.9x1.9 hole 1.4: 1(-2.54,0)
  round 1.9 hole 1.4: 3(2.54,0)
  silkscreen extent -5.25,-1.64 5.26,3.01, body extent -5.25,-1.64 5.26,3.01, height 19.09
VAR_S10K275E2 [mm] "EPCOS"
  round 1.6 hole 1.1: 1(-3.75,1.1) 2(3.75,-1.1)
  silkscreen extent -6,-2.7 6,2.7, body extent -5.98,-2.7 5.98,2.7, height 14.99
WE-FI_2750x1300 [mm] "TH, 2-Leads, Dia 27.5mm, T 13mm, Lead Spacing 12mm"
  round 1.75 hole 1.25: 1(-6,0) 2(6,0)
  silkscreen extent -6.5,-13.74 6.5,13.75, body extent -6.5,-13.74 6.5,13.74, height 27.37
WE-PD4-S [mm] "Wurth Elektronik recommended land pattern 2004-10-11"
  rect 1.4x3.56 smd: 1(-2.73,0) 2(2.73,0)
  silkscreen extent -3.75,-2.22 3.75,2.22, body extent -3.3,-2.23 3.3,2.23, height 2.92
WSL2512_-0005 [mm]
  rect 3.05x3.68 smd: 1(-2.16,0) 2(2.16,0)
  silkscreen extent -0.3,-1.8 0.3,1.8, body extent -3.3,-1.71 3.3,1.71, height 0.89
WURTH_7448031501 [mm] "FILTER, COMMON MODE CHOKE, VERTICAL, TH-4P"
  rect 2.1x2.1 / inner round 2.1 / far side rect 2.1x2.1 hole 1.6: 1(-3.75,-5.35)
  round 2.1 hole 1.6: 2(3.75,-5.35) 3(3.75,5.35) 4(-3.75,5.35)
  silkscreen extent -12.09,-8.5 11.5,8.5, body extent -11.5,-8.5 11.5,8.5, height 25

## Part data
C1A C1B C1C: library part CMP-in_PMP30763, "270µF 350V Aluminum Electrolytic Capacitors Radial, Can - Snap-In  2000 Hrs @ 85°C", Digikey Part Number=493-7111-ND, Leakage Current=920uA, Manufacturer=Nichicon, Mouser Part Number=647-LGN2V271MELB25, Operating Temperature Range="-25°C to +85°C", Tolerance_%=20%, ValueDisplayed=270uF
C2 C3: library part B32652A7153J000, "CAP FILM 0.047UF 10% 630VDC RAD", Cap_Case=18x8x12.5, Manufacturer="EPCOS (TDK)", Supplier Part Number 1=495-7186-ND, Tolerance_%=5, Value2=630V, ValueDisplayed=0.068µF
C4 C5 C61: library part CMP-0012558-3, "0.33µF Film Capacitor 450V Polypropylene (PP), Metallized Radial", Cap_Case=13x12x6, Manufacturer="Panasonic Electronic Components", Supplier Part Number 1=399-9643-ND, Tolerance_%=10%, Value1=Unknown, Value2=450V, ValueDisplayed=0.33µF
C6 C8 C11 C47 C49: library part CMP-0009587-2, "CAP, CERM, 2200 pF, 300 V, +/- 20%, Y5U, AEC-Q200 Grade 1, D9.5xT5mm", Cap_Case=9.5x5mm, Manufacturer=Vishay-Bccomponents, PartNumber=AY2222M35Y5US63L7, Supplier Part Number 1=BC2914-ND, TempCo=Y5U, Tolerance_%=20%, Value1=Unknown, Value2=300V, ValueDisplayed=2200pF
C7 C65: library part CMP-0009273-2, "CAP, CERM, 0.01 uF, 500 V, +/- 10%, X7R, 1210", Cap_Case=1210, Manufacturer=Vishay-Vitramon, Supplier Part Number 1=720-1046-1-ND, TempCo=X7R, Tolerance_%=10%, Value1=Unknown, Value2=500V, ValueDisplayed=0.01uF
C9 C10: library part CMP-0012409-3, "CAP, Film, 0.33 uF, 630 V, +/- 10%, TH", Cap_Case=18x8x14.5mm, Manufacturer=TDK, PartNumber=B32922C3334K, Supplier Part Number 1=495-5051-ND, Tolerance_%=10%, Value1=Unknown, Value2=630V, ValueDisplayed=0.33uF
C12 C13 C14 C76: library part CMP-0083624-1, "CAP, AL, 680 µF, 50 V, +/- 20%, TH", Cap_Case=12.5x25mm, Manufacturer=Panasonic, Supplier Part Number 1=P122333CT-ND, Tolerance_%=20%, Value2=50V, ValueDisplayed=680µF
C15 C30 C55 C57: library part CMP-0007405-4, "CAP, CERM, 1 uF, 25 V, +/- 10%, X7R, 0603", Cap_Case=0603, Manufacturer=MuRata, PartNumber=GRM188R71E105KA12D, Supplier Part Number 1=490-5307-1-ND, TempCo=X7R, Tolerance_%=10%, Value1=Unknown, Value2=25V, ValueDisplayed=1uF
C16 C27 C28 C32 C52 C63: library part CMP-0007044-5, "CAP, CERM, 0.1 uF, 50 V, +/- 10%, X7R, 0603", Cap_Case=0603, Manufacturer=TDK, Supplier Part Number 1=445-1314-1-ND, TempCo=X7R, Tolerance_%=10%, Value1="0.0296 ohm", Value2=50V, ValueDisplayed=0.1uF
C17 C34: library part CMP-0007377-4, "CAP, CERM, 0.01 uF, 16 V, +/- 10%, X7R, 0603", Cap_Case=0603, Manufacturer=MuRata, Supplier Part Number 1=490-1525-1-ND, TempCo=X7R, Tolerance_%=10%, Value1=Unknown, Value2=16V, ValueDisplayed=0.01uF
C18: library part C0603C101J5GAC, "CAP CER 100PF 16V C0G/NP0 0603", Cap_Case=0603, Manufacturer="Wurth Electronics Inc.", Supplier Part Number 1=732-7766-1-ND, TempCo=C0G/NP0, Tolerance_%=5, Value1=Unknown, Value2=16V, ValueDisplayed=100pF
C19: library part CMP-0007612-2, "CAP, CERM, 3.3 pF, 50 V, +/- 8%, C0G/NP0, 0805", Cap_Case=0805, Manufacturer=AVX, PartNumber=08055A3R3CAT2A, Supplier Part Number 1=478-1298-1-ND, TempCo=C0G/NP0, Tolerance_%=8%, Value1="3.467 ohm", Value2=50V, ValueDisplayed=3.3pF
C20 C50: library part CMP-0006761-4, "CAP, CERM, 10 pF, 50 V, +/- 5%, C0G/NP0, 0603", Cap_Case=0603, Manufacturer=AVX, PartNumber=06035A100JAT2A, Supplier Part Number 1=478-1163-1-ND, TempCo=C0G/NP0, Tolerance_%=5%, Value1="0.403 ohm", Value2=50V, ValueDisplayed=10pF
C21: library part CMP-0007180-4, "CAP, CERM, 1200 pF, 50 V, +/- 5%, C0G/NP0, 0603", Cap_Case=0603, Manufacturer=MuRata, Supplier Part Number 1=490-1453-1-ND, TempCo=C0G/NP0, Tolerance_%=5%, Value1=Unknown, Value2=50V, ValueDisplayed=1200pF
C22: library part CMP-0007465-4, "CAP, CERM, 8200 pF, 50 V, +/- 10%, X7R, 0603", Cap_Case=0603, Manufacturer=MuRata, Supplier Part Number 1=490-1510-1-ND, TempCo=X7R, Tolerance_%=10%, Value1=Unknown, Value2=50V, ValueDisplayed=8200pF
C23 C59: library part CMP-0007573-2, "CAP, CERM, 2.2 uF, 25 V, +/- 10%, X7R, 0805", Cap_Case=0805, Manufacturer=AVX, Supplier Part Number 1=478-5719-1-ND, TempCo=X7R, Tolerance_%=10%, Value1=Unknown, Value2=25V, ValueDisplayed=2.2uF
C24 C25: library part CMP-0006919-4, "CAP, CERM, 33 pF, 50 V, +/- 5%, C0G/NP0, 0603", Cap_Case=0603, Manufacturer=Kemet, Supplier Part Number 1=399-1055-1-ND, TempCo=C0G/NP0, Tolerance_%=5%, Value1=Unknown, Value2=50V, ValueDisplayed=33pF
C26: library part CMP-0007722-2, "CAP, CERM, 0.1 uF, 100 V, +/- 10%, X7R, 0805", Cap_Case=0805, Manufacturer=Kemet, PartNumber=C0805C104K1RACTU, Supplier Part Number 1=399-3486-1-ND, TempCo=X7R, Tolerance_%=10%, Value1="0.064 ohm", Value2=100V, ValueDisplayed=0.1uF
C29: "CAP, CERM, 1000 pF, 50 V, +/- 10%, X7R, 0603", Cap_Case=0603, Manufacturer=TDK, Supplier Part Number 1=445-1308-1-ND, TempCo=X7R, Tolerance_%=10, Value1="0.24 ohm", Value2=50V, ValueDisplayed=1000pF
C31 C64: library part CMP-0007050-4, "CAP, CERM, 0.47 uF, 50 V, +/- 10%, X7R, 0603", Cap_Case=0603, Manufacturer=TDK, Supplier Part Number 1=445-5952-1-ND, TempCo=X7R, Tolerance_%=10%, Value1="0.010974 ohm", Value2=50V, ValueDisplayed=0.47uF
C33: library part CMP-0007221-4, "CAP, CERM, 470 pF, 50 V, +/- 5%, C0G/NP0, 0603", Cap_Case=0603, Manufacturer=MuRata, Supplier Part Number 1=490-1443-1-ND, TempCo=C0G/NP0, Tolerance_%=5%, Value1=Unknown, Value2=50V, ValueDisplayed=470pF
C35 C56: library part CMP-0007347-5, "CAP, CERM, 4.7 uF, 25 V, +/- 10%, X5R, 0603", Cap_Case=0603, Manufacturer=MuRata, Supplier Part Number 1=490-7203-1-ND, TempCo=X5R, Tolerance_%=10%, Value1=Unknown, Value2=25V, ValueDisplayed=4.7uF
C36: library part CMP-0007375-4, "CAP, CERM, 0.68 uF, 16 V, +/- 10%, X7R, 0603", Cap_Case=0603, Manufacturer=Samsung, Supplier Part Number 1=1276-2114-1-ND, TempCo=X7R, Tolerance_%=10%, Value1=Unknown, Value2=16V, ValueDisplayed=0.68uF
C37: library part CMP-0007180-4, Cap_Case=0603, TempCo=C0G/NP0, Tolerance_%=5%, Value1=Unknown, Value2=50V
C38: library part CMP-0007445-4, "CAP, CERM, 0.22 uF, 50 V, +/- 10%, X7R, 0603", Cap_Case=0603, Manufacturer=MuRata, Supplier Part Number 1=490-12546-1-ND, TempCo=X7R, Tolerance_%=10%, Value1=Unknown, Value2=50V, ValueDisplayed=0.22uF
C39: library part CMP-0008898-2, "CAP, CERM, 150 pF, 1000 V, +/- 5%, U2J, 1206", Cap_Case=1206, Manufacturer=MuRata, PartNumber=GRM31A7U3A151JW31D, Supplier Part Number 1=490-4302-1-ND, TempCo=U2J, Tolerance_%=5%, Value1=Unknown, Value2=1000V, ValueDisplayed=150pF
C40: library part GRM31A7U3A151JW31D, "CAP CER 82PF 1KV U2J 1206", Cap_Case=1206, Manufacturer=MuRata, Supplier Part Number 1=490-8332-1-ND, TempCo=U2J, Tolerance_%=5, Value1=Unknown, Value2=1000V, ValueDisplayed=82pF
C41: library part CMP-0007053-4, "CAP, CERM, 1000 pF, 100 V, +/- 10%, X7R, 0603", Cap_Case=0603, Manufacturer=TDK, Supplier Part Number 1=445-1298-1-ND, TempCo=X7R, Tolerance_%=10%, Value1=Unknown, Value2=100V, ValueDisplayed=1000pF
C42: library part CMP-0006757-5, "CAP, CERM, 0.047 uF, 25 V, +/- 5%, X7R, 0603", Cap_Case=0603, Manufacturer=AVX, Supplier Part Number 1=478-3716-1-ND, TempCo=X7R, Tolerance_%=5%, Value1="0.052 ohm", Value2=25V, ValueDisplayed=0.047uF
C43: library part CMP-0007461-4, "CAP, CERM, 680 pF, 50 V, +/- 10%, X7R, 0603", Cap_Case=0603, Manufacturer=MuRata, PartNumber=GRM188R71H681KA01D, Supplier Part Number 1=490-1491-1-ND, TempCo=X7R, Tolerance_%=10%, Value1=Unknown, Value2=50V, ValueDisplayed=680pF
C44 C45: library part CMP-0008475-2, "CAP, CERM, 330 pF, 100 V, +/- 5%, C0G/NP0, 1206", Cap_Case=1206, Manufacturer=AVX, Supplier Part Number 1=478-1447-1-ND, TempCo=C0G/NP0, Tolerance_%=5%, Value1="0.392 ohm", Value2=100V, ValueDisplayed=330pF
C46 C48: library part CMP-0007728-2, "CAP, CERM, 1 uF, 25 V, +/- 10%, X7R, 0805", Cap_Case=0805, Manufacturer=Kemet, PartNumber=C0805C105K3RACTU, Supplier Part Number 1=399-8004-1-ND, TempCo=X7R, Tolerance_%=10%, Value1=Unknown, Value2=25V, ValueDisplayed=1uF
C51: library part CMP-0008863-2, "CAP, CERM, 1 uF, 25 V, +/- 10%, X5R, 1206", Cap_Case=1206, Manufacturer=MuRata, PartNumber=GRM319R61E105KC36D, Supplier Part Number 1=490-1807-1-ND, TempCo=X5R, Tolerance_%=10%, Value1="0.01 ohm", Value2=25V, ValueDisplayed=1uF
C53 C54: library part CMP-0007356-5, "CAP, CERM, 2.2 uF, 35 V, +/- 10%, X5R, 0603", Cap_Case=0603, Manufacturer=MuRata, Supplier Part Number 1=490-7204-6-ND, TempCo=X5R, Tolerance_%=10%, Value1=Unknown, Value2=35V, ValueDisplayed=2.2uF
C58 C62: library part CMP-0006763-4, "CAP, CERM, 100 pF, 50 V, +/- 5%, C0G/NP0, 0603", Cap_Case=0603, Manufacturer=AVX, Supplier Part Number 1=478-1175-1-ND, TempCo=C0G/NP0, Tolerance_%=5%, Value1="0.119 ohm", Value2=50V, ValueDisplayed=100pF
C60: library part CMP-0064896-2, "1000µF 35V Aluminum Electrolytic Capacitors Radial, Can 10000 Hrs @ 105°C", Cap_Case=10x12.5, Manufacturer=Panasonic, Supplier Part Number 1=P10323-ND, Tolerance_%=20%, Value2=35V, ValueDisplayed=1000µF
C67 C68 C72 C73: library part CMP-0009135-2, "CAP, CERM, 4.7 uF, 100 V, +/- 10%, X7S, 1210", Cap_Case=1210, Manufacturer=TDK, PartNumber=C3225X7S2A475K200AE, Supplier Part Number 1=445-8912-1-ND, TempCo=X7S, Tolerance_%=10%, Value1=Unknown, Value2=100V, ValueDisplayed=4.7uF
C100 C101: library part CMP-0008236-2, "CAP, CERM, 100 pF, 250 V, +/- 5%, C0G/NP0, 0805", Cap_Case=0805, Manufacturer=MuRata, Supplier Part Number 1=490-5542-1-ND, TempCo=C0G/NP0, Tolerance_%=5%, Value1=Unknown, Value2=250V, ValueDisplayed=100pF
D1 D5: library part CMP-0029037-2, "Diode, Ultrafast, 600 V, 8 A, TH", Manufacturer="ON Semiconductor", Value1=8A, Value2=0.98V
D2 D6 D12 D13 D15: library part CMP-0028455-2, "Diode, Schottky, 30 V, 0.2 A, SOD-323", Manufacturer="ON Semiconductor", Value1=0.2A, Value2=0.35V
D3: library part GBU4A-BP, "RECT BRIDGE GPP 1000V 25A GBU", Manufacturer="Comchip Technology", Value1=8A, Value2=50V
D4: library part CMP-0005844-4, "Diode, Zener, 15 V, 300 mW, SOD-323", Manufacturer="NXP Semiconductor", Power_W=300mW, Value1=0.3W
D7 D8: library part CMP-0028545-2, "Diode, Schottky, 30 V, 0.35 A, SOD-123", Manufacturer="Diodes Inc.", PartNumber=SD103BW-7-F, Value1=0.35A, Value2=0.55V
D9 D10: library part CMP-0076889-2, "Diode, P-N, 1000 V, 1 A, SMB", Manufacturer="Diodes Inc.", PartNumber=RS1MB-13-F, Value2=1.3V
D11: library part CMP-0028377-2, "Diode, Schottky, 60 V, 1 A, SOD-123F", Manufacturer=Nexperia, Value1=1A, Value2=0.57V
D14: library part CMP-0029150-2, "Diode, Switching, 200 V, 0.2 A, AEC-Q101, SOD-323", Manufacturer="ON Semiconductor", Value1=0.2A, Value2=1.25V
D18: library part CMP-0077027-2, "Diode, Ultrafast, 600 V, 1 A, SMA", Manufacturer="Diodes Inc.", PartNumber=US1J-13-F, Value2=1.7V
